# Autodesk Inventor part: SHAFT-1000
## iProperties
Created: 2007-08
Part Number: SHAFT-1000
Material: Stainless Steel
Document SubType Name: Modeling
Density: 8.08 g/cm^3
Mass: 2.05689 g
Surface Area: 3.30995 cm^2
Volume: 0.254566 cm^3
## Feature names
1. Base1
2. Split1
